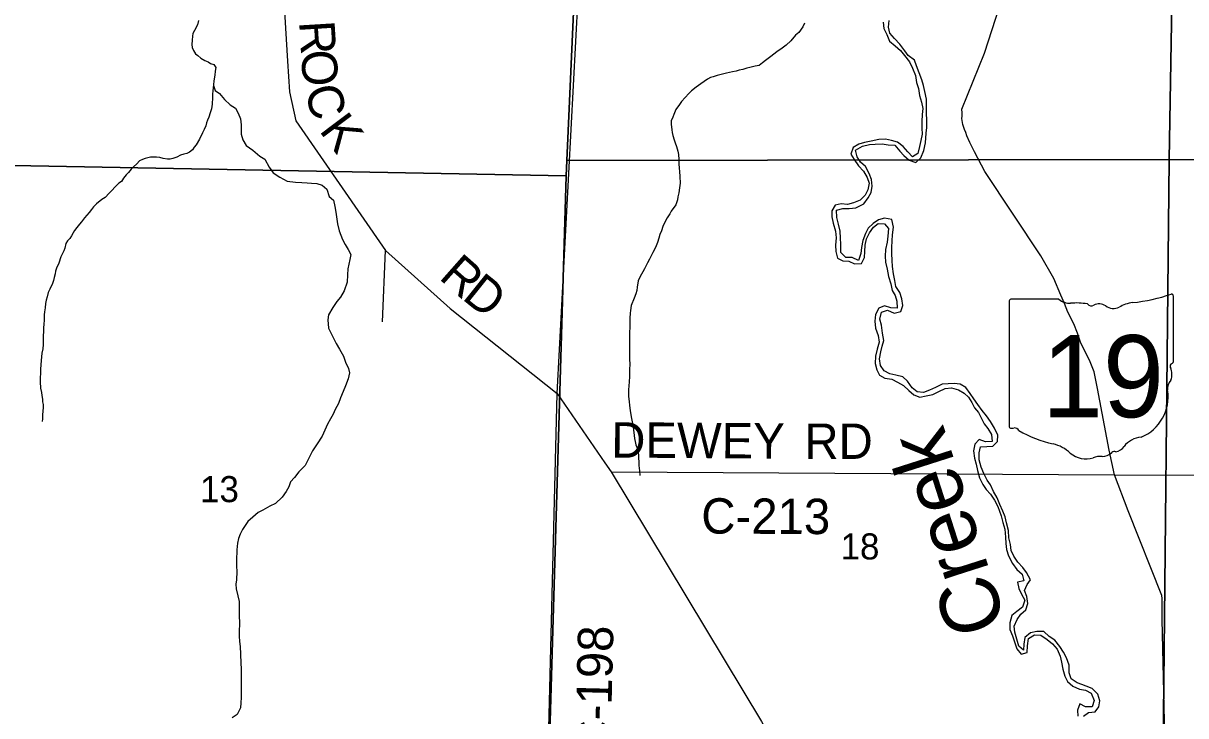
# Model space of a CAD drawing. Extents: x 0 to 34, y 0 to 22.
# Drawn here: x 25.144 to 27.011, y 17.024 to 18.136 of the extents above; entities that cross this region are included whole.
import ezdxf

# ---------------------------------------------------------------- set-up
doc = ezdxf.new("R2010")
doc.units = 0
for name, color, linetype in [('GM_X_County_Road', 7, 'Continuous'), ('GM_X_County_Road_Text', 7, 'Continuous'), ('GM_X_Minor_River', 7, 'Continuous'), ('GM_X_Minor_River_Text', 7, 'Continuous'), ('GM_X_Section', 7, 'Continuous'), ('GM_X_Section_Text', 7, 'Continuous'), ('GM_X_State_Location', 7, 'Continuous'), ('GM_X_State_Route', 7, 'Continuous'), ('GM_X_State_Shield', 7, 'Continuous'), ('GM_X_Township_Road', 7, 'Continuous')]:
    doc.layers.add(name, color=color, linetype=linetype)

msp = doc.modelspace()

# ---------------------------------------------------------------- linework, layer by layer
at = {"layer": 'GM_X_County_Road'}
for p, q in [((26.0016, 17.5418), (26.0471, 18.3979)), ((25.9854, 16.8861), (26.0016, 17.5418)), ((26.0883, 17.4156), (26.8961, 17.4108))]:
    msp.add_line(p, q, dxfattribs=at)
for points in [[(25.567, 18.4152), (25.5646, 18.2951), (25.5618, 18.1907), (25.5686, 18.0751), (25.5717, 18.0261), (25.5819, 17.9792), (25.7259, 17.7714), (25.8295, 17.6782), (26.0016, 17.5418)], [(26.0016, 17.5418), (26.078, 17.4304), (26.0883, 17.4156)], [(26.0883, 17.4156), (26.3294, 17.015), (26.4602, 16.7846), (26.4794, 16.7319), (26.4973, 16.6609), (26.566, 16.4258)], [(26.8961, 17.4108), (27.2508, 17.4104), (27.9854, 17.4096)]]:
    msp.add_lwpolyline(points, dxfattribs=at)
at = {"layer": 'GM_X_Minor_River'}
for points in [[(25.4255, 18.1407), (25.4239, 18.1335), (25.4192, 18.1248), (25.4165, 18.1199), (25.4161, 18.1157), (25.4152, 18.1089), (25.4148, 18.1021), (25.4155, 18.0975), (25.4177, 18.0922), (25.4207, 18.0872), (25.4248, 18.0842), (25.4293, 18.0799), (25.4357, 18.0764), (25.441, 18.0741), (25.4451, 18.0714), (25.4504, 18.0698), (25.4534, 18.0652), (25.4526, 18.0592), (25.4521, 18.0527), (25.4501, 18.0436), (25.4497, 18.0372), (25.4484, 18.0277), (25.448, 18.0224), (25.4479, 18.0167)], [(26.3984, 18.1363), (26.3957, 18.1303), (26.3895, 18.1216), (26.3841, 18.1168), (26.3764, 18.1081), (26.3692, 18.101), (26.3626, 18.0961), (26.3542, 18.0901), (26.3443, 18.083), (26.3359, 18.0763), (26.3309, 18.0725), (26.3259, 18.0684), (26.3195, 18.067), (26.3107, 18.0652), (26.3058, 18.0641), (26.2993, 18.0619), (26.2936, 18.0608), (26.289, 18.0593), (26.2829, 18.0579), (26.2734, 18.0561), (26.267, 18.0543), (26.2582, 18.0521), (26.2521, 18.0502), (26.2475, 18.0488), (26.2426, 18.0465), (26.2372, 18.0428), (26.2323, 18.0391), (26.2246, 18.0338), (26.2173, 18.0278), (26.2127, 18.0233), (26.2012, 18.0105), (26.1977, 18.0056), (26.192, 17.9977), (26.1885, 17.9898), (26.1869, 17.9853), (26.1845, 17.9796), (26.1845, 17.9743), (26.1855, 17.9652), (26.1862, 17.9606), (26.1873, 17.956), (26.1891, 17.9488), (26.191, 17.9439), (26.1928, 17.9385), (26.1954, 17.9305), (26.1964, 17.9252), (26.1967, 17.9172), (26.1967, 17.9104), (26.1973, 17.9036), (26.1976, 17.8979), (26.1983, 17.8903), (26.199, 17.8792), (26.1977, 17.872), (26.1969, 17.8637), (26.1949, 17.8573), (26.1945, 17.8527), (26.1921, 17.8448), (26.1844, 17.8346), (26.1825, 17.8301), (26.1778, 17.8237), (26.1736, 17.8154), (26.1712, 17.8097), (26.1689, 17.8029), (26.1665, 17.7968), (26.1649, 17.7908), (26.1626, 17.784), (26.1591, 17.7761)], [(26.5236, 17.6382), (26.522, 17.6515), (26.5196, 17.6611), (26.5222, 17.6724), (26.5318, 17.6756), (26.5423, 17.6703), (26.5534, 17.6735), (26.5563, 17.6829), (26.555, 17.6935), (26.5515, 17.7035), (26.5453, 17.7132), (26.5433, 17.7231), (26.5413, 17.7338), (26.5398, 17.7456), (26.5393, 17.7551), (26.5388, 17.7665), (26.5387, 17.776), (26.5394, 17.7866), (26.54, 17.7965), (26.5415, 17.8086), (26.5388, 17.8212), (26.5271, 17.8234), (26.5171, 17.8206), (26.509, 17.8144), (26.5009, 17.807), (26.4964, 17.7984), (26.4924, 17.7875), (26.4898, 17.7762), (26.4887, 17.7663), (26.4854, 17.7554), (26.4749, 17.7599), (26.4651, 17.7598), (26.4569, 17.768), (26.4569, 17.7816), (26.4561, 17.7912), (26.4556, 17.8022), (26.4529, 17.8133), (26.4505, 17.8243), (26.4501, 17.8361), (26.46, 17.8385), (26.4702, 17.8386), (26.4809, 17.8398), (26.4939, 17.8459), (26.5006, 17.8556), (26.5058, 17.8646), (26.5072, 17.8748), (26.506, 17.8851), (26.5025, 17.8951), (26.4963, 17.9062), (26.4886, 17.9129), (26.4831, 17.9218), (26.4804, 17.9325), (26.4915, 17.9386), (26.5026, 17.9414), (26.5121, 17.9422), (26.5231, 17.9427), (26.5329, 17.9409), (26.5435, 17.9406), (26.5516, 17.9309), (26.5582, 17.9239), (26.5668, 17.9164), (26.5773, 17.9127), (26.5851, 17.9201), (26.5899, 17.9318), (26.5925, 17.9442), (26.5941, 17.9594), (26.5951, 17.9688), (26.5947, 17.9806), (26.5946, 17.9916), (26.5945, 18.0022), (26.5944, 18.0144), (26.5917, 18.0266), (26.5893, 18.0362), (26.5869, 18.0454), (26.5827, 18.0565), (26.5784, 18.0676), (26.5749, 18.0768), (26.5652, 18.0843), (26.5594, 18.0921), (26.5513, 18.1025), (26.5432, 18.1119), (26.5355, 18.1204), (26.5335, 18.13), (26.5342, 18.1406)], [(26.525, 18.1382), (26.5259, 18.1279), (26.5309, 18.1179), (26.5348, 18.1075), (26.544, 18.0997), (26.5526, 18.0922), (26.5592, 18.0845), (26.5669, 18.0744), (26.5719, 18.064), (26.5765, 18.0521), (26.5785, 18.041), (26.5813, 18.0315), (26.5832, 18.02), (26.5864, 18.0097), (26.5884, 17.9994), (26.5873, 17.9895), (26.587, 17.9782), (26.5867, 17.9679), (26.5872, 17.958), (26.5851, 17.9478), (26.5829, 17.9384), (26.5807, 17.9271), (26.5718, 17.9216), (26.5645, 17.9298), (26.5567, 17.9384), (26.5478, 17.9451), (26.5384, 17.948), (26.5286, 17.9498), (26.5176, 17.9497), (26.5058, 17.947), (26.4951, 17.9446), (26.4859, 17.9418)], [(25.4496, 18.0362), (25.4522, 18.0284), (25.4594, 18.0234), (25.4672, 18.0135), (25.4766, 18.0054), (25.4849, 18), (25.4894, 17.992), (25.4931, 17.9828), (25.4941, 17.9733), (25.4939, 17.9578), (25.4969, 17.949), (25.5021, 17.9399), (25.513, 17.9321), (25.5239, 17.9229), (25.5322, 17.9179), (25.5392, 17.9049), (25.5456, 17.8961), (25.5561, 17.8892), (25.5682, 17.8826), (25.5814, 17.8809), (25.5917, 17.8804), (25.6, 17.88), (25.6072, 17.8795), (25.6155, 17.879), (25.6242, 17.8763), (25.6314, 17.8698), (25.6354, 17.858), (25.6425, 17.8522), (25.6447, 17.8419), (25.6461, 17.8328), (25.6486, 17.8142), (25.6515, 17.8028), (25.6566, 17.789), (25.6611, 17.781), (25.6659, 17.7726), (25.67, 17.765), (25.6688, 17.7566), (25.6652, 17.7415), (25.6647, 17.732), (25.6642, 17.7206), (25.6595, 17.7066), (25.6537, 17.6965), (25.6475, 17.6893), (25.6413, 17.6799), (25.6344, 17.6678), (25.6331, 17.6599), (25.6345, 17.6462), (25.639, 17.637), (25.6467, 17.6221), (25.652, 17.613), (25.6583, 17.6015), (25.6616, 17.592), (25.6664, 17.5817), (25.6678, 17.5745), (25.6658, 17.565), (25.6615, 17.554), (25.658, 17.5446), (25.6537, 17.5344), (25.6506, 17.5257), (25.6448, 17.5159), (25.6417, 17.5083), (25.6374, 17.5008), (25.6327, 17.4925), (25.6242, 17.4732), (25.6161, 17.4608), (25.6084, 17.4495), (25.601, 17.4347), (25.5967, 17.4261), (25.5867, 17.4155), (25.5798, 17.4065), (25.5733, 17.3994), (25.5705, 17.3918), (25.5666, 17.3839), (25.5601, 17.3748), (25.5494, 17.3651), (25.5402, 17.3606), (25.5287, 17.3539), (25.5215, 17.3506), (25.5131, 17.3431), (25.505, 17.336), (25.4962, 17.3231), (25.4927, 17.3156), (25.4899, 17.3084), (25.4883, 17.3012), (25.4871, 17.2906), (25.4865, 17.2731), (25.4868, 17.2644), (25.4874, 17.2557), (25.4865, 17.2424), (25.4853, 17.2352), (25.4863, 17.228), (25.4885, 17.2166), (25.491, 17.2074), (25.4908, 17.185), (25.4914, 17.1729), (25.4909, 17.1589), (25.4908, 17.1513), (25.4915, 17.144), (25.4925, 17.1349), (25.4931, 17.1232), (25.4937, 17.108)], [(25.4479, 18.0167), (25.4474, 18.0065), (25.4466, 17.9989), (25.4442, 17.9925), (25.4423, 17.9853), (25.4403, 17.9804), (25.4384, 17.9762), (25.4376, 17.9713), (25.4348, 17.9656), (25.4321, 17.96), (25.4271, 17.9501), (25.4217, 17.9411), (25.4186, 17.937), (25.4159, 17.9328), (25.4113, 17.9291), (25.4071, 17.9268), (25.4018, 17.9257), (25.3968, 17.9243), (25.3907, 17.9213), (25.3842, 17.9191), (25.38, 17.918), (25.3759, 17.9177), (25.3687, 17.9189), (25.3638, 17.9205), (25.3581, 17.9213), (25.3528, 17.9213), (25.3486, 17.921), (25.3444, 17.9199), (25.3398, 17.9188), (25.3357, 17.9173), (25.3311, 17.9151), (25.3265, 17.9102), (25.3211, 17.9057), (25.3173, 17.9016), (25.3134, 17.8967), (25.3096, 17.8926), (25.305, 17.8873), (25.3019, 17.882), (25.2977, 17.8794), (25.2919, 17.8734), (25.2865, 17.8674), (25.2823, 17.8633), (25.2758, 17.8565), (25.2704, 17.8531), (25.262, 17.8464), (25.257, 17.8415), (25.2539, 17.837), (25.2501, 17.8321), (25.2463, 17.828), (25.2428, 17.8238), (25.2378, 17.8174), (25.2343, 17.8133), (25.2301, 17.808), (25.2266, 17.8035), (25.2243, 17.7994), (25.2216, 17.7948), (25.2189, 17.7907), (25.2154, 17.7866), (25.2127, 17.7824), (25.2108, 17.7752), (25.2092, 17.7707), (25.2068, 17.7654), (25.2045, 17.7609), (25.2014, 17.7506), (25.1979, 17.7427), (25.1963, 17.7378), (25.1955, 17.7336), (25.1939, 17.7276), (25.1927, 17.723), (25.1911, 17.7181), (25.1872, 17.709), (25.1845, 17.7038), (25.1825, 17.697), (25.181, 17.6913), (25.1802, 17.6863), (25.1793, 17.6791), (25.1785, 17.6727), (25.178, 17.6678), (25.1776, 17.6598), (25.1771, 17.6526), (25.1767, 17.6473), (25.1764, 17.6279), (25.176, 17.6204), (25.1755, 17.6135), (25.1743, 17.6063), (25.1735, 17.6006), (25.173, 17.5946), (25.1726, 17.5878), (25.1721, 17.5805), (25.172, 17.5737), (25.1716, 17.5673), (25.1715, 17.5601), (25.1721, 17.5502), (25.1736, 17.5433), (25.1743, 17.5384), (25.175, 17.5323), (25.1753, 17.5281), (25.176, 17.5236), (25.176, 17.5186), (25.1755, 17.5137), (25.1751, 17.5065)], [(26.4859, 17.9418), (26.4767, 17.9368), (26.473, 17.9259), (26.4781, 17.9174), (26.4854, 17.9073), (26.4931, 17.8987), (26.4993, 17.8883), (26.5024, 17.8791), (26.5003, 17.8689), (26.4958, 17.8603), (26.4877, 17.8522), (26.4773, 17.8479), (26.4674, 17.8451), (26.4575, 17.8462), (26.4476, 17.8442), (26.4424, 17.8348), (26.4426, 17.8253), (26.4446, 17.815), (26.4484, 17.8024), (26.4496, 17.7913), (26.4485, 17.7796), (26.4486, 17.7697), (26.4514, 17.759), (26.46, 17.7546), (26.4698, 17.7543), (26.4788, 17.7499), (26.4898, 17.7504), (26.4946, 17.7601), (26.4953, 17.7696), (26.4959, 17.7798), (26.4981, 17.79), (26.5029, 17.7994), (26.5092, 17.8087), (26.517, 17.8145), (26.5272, 17.8143), (26.5334, 17.8065), (26.5324, 17.794), (26.5313, 17.7845), (26.5287, 17.7728), (26.5281, 17.7622), (26.5286, 17.7523), (26.5313, 17.7413), (26.5336, 17.7294), (26.5371, 17.7179), (26.5391, 17.7069), (26.5442, 17.6988), (26.547, 17.6896), (26.5474, 17.6786), (26.5372, 17.6792), (26.5267, 17.6825), (26.5178, 17.6786), (26.5123, 17.6685), (26.5116, 17.6579), (26.5124, 17.6465), (26.5167, 17.6346), (26.5183, 17.6239), (26.5153, 17.6126), (26.5123, 17.6013), (26.512, 17.5895), (26.5144, 17.5796), (26.5191, 17.5711), (26.5277, 17.566), (26.5386, 17.5645), (26.548, 17.5597), (26.5577, 17.5545), (26.5658, 17.5463), (26.574, 17.5396), (26.5837, 17.5356), (26.5937, 17.5379), (26.6043, 17.5399), (26.6143, 17.5446), (26.6243, 17.5496), (26.6346, 17.5509), (26.6455, 17.5475), (26.6548, 17.5423), (26.6619, 17.5357), (26.6673, 17.5272), (26.6716, 17.5187), (26.6779, 17.511), (26.6825, 17.5013), (26.6872, 17.4929), (26.6931, 17.4851), (26.6985, 17.4755), (26.6997, 17.4644), (26.6891, 17.4639), (26.679, 17.4676), (26.6719, 17.4599), (26.6698, 17.4497), (26.6713, 17.4375), (26.6741, 17.4283), (26.6761, 17.4176), (26.6796, 17.4061), (26.685, 17.3953), (26.6901, 17.3872), (26.6971, 17.3798), (26.7036, 17.3702), (26.7087, 17.3598), (26.714, 17.3452), (26.7171, 17.3345), (26.7202, 17.3234), (26.721, 17.3108)], [(26.1591, 17.7761), (26.1548, 17.7681), (26.1521, 17.7628), (26.1494, 17.7572), (26.1467, 17.7515), (26.1416, 17.7417), (26.1389, 17.7368), (26.1346, 17.7292), (26.1315, 17.7224), (26.1299, 17.7122), (26.1295, 17.7069), (26.1275, 17.7016), (26.1248, 17.6944), (26.1201, 17.6827), (26.1189, 17.6751), (26.1184, 17.6706), (26.118, 17.6626), (26.1182, 17.6524), (26.1182, 17.6478), (26.1177, 17.6402), (26.1173, 17.6019), (26.1176, 17.5962), (26.1179, 17.5894), (26.1178, 17.5795), (26.1173, 17.57), (26.1172, 17.5594), (26.1167, 17.5548), (26.1162, 17.5461), (26.1161, 17.537), (26.1168, 17.5283), (26.1175, 17.5226), (26.1182, 17.518), (26.1193, 17.5104), (26.1207, 17.5013), (26.1232, 17.488), (26.1239, 17.4834), (26.1249, 17.4739), (26.1256, 17.4693), (26.1267, 17.4644), (26.1278, 17.4591), (26.1304, 17.4526), (26.1318, 17.4431), (26.1321, 17.4385), (26.1328, 17.4306), (26.1327, 17.426), (26.1334, 17.4173), (26.1344, 17.4097)], [(26.5893, 17.543), (26.5794, 17.5444), (26.5716, 17.5507), (26.5636, 17.5612), (26.5566, 17.5682), (26.5453, 17.5712), (26.5355, 17.5733), (26.5265, 17.5778), (26.5207, 17.5867), (26.5191, 17.5973), (26.5212, 17.6083), (26.523, 17.6177), (26.5259, 17.6268), (26.5236, 17.6382)], [(26.8463, 17.0234), (26.8544, 17.0292), (26.8651, 17.0305), (26.8713, 17.0383), (26.8728, 17.0481), (26.8696, 17.0588), (26.8604, 17.0678), (26.8509, 17.0714), (26.8436, 17.0742), (26.836, 17.0768), (26.8267, 17.0832), (26.8235, 17.0927), (26.8235, 17.1053), (26.8189, 17.1168), (26.8142, 17.126), (26.8084, 17.1353), (26.8003, 17.1454), (26.7914, 17.1513), (26.7829, 17.1595), (26.7715, 17.1591), (26.7612, 17.1571), (26.7523, 17.1494), (26.7508, 17.1392), (26.7502, 17.1293), (26.7428, 17.1356), (26.7393, 17.1471), (26.7362, 17.1582), (26.7353, 17.1677), (26.7398, 17.1786), (26.7457, 17.1871), (26.7538, 17.1941), (26.7568, 17.2043), (26.7556, 17.2157), (26.7517, 17.2249), (26.7561, 17.2347), (26.7616, 17.2425), (26.7551, 17.2541), (26.7492, 17.2622), (26.7411, 17.2708), (26.7346, 17.2805), (26.7303, 17.2893), (26.729, 17.2988), (26.7267, 17.3099), (26.7258, 17.3217), (26.7228, 17.3339), (26.7207, 17.3435), (26.7168, 17.3523), (26.7122, 17.3631), (26.7079, 17.3742), (26.7021, 17.3842), (26.6971, 17.3946), (26.6916, 17.4024), (26.6862, 17.4128), (26.6819, 17.4231), (26.6788, 17.435), (26.6788, 17.4464), (26.6813, 17.4558), (26.6912, 17.4563), (26.7007, 17.4568), (26.7081, 17.4646), (26.7091, 17.4744), (26.7037, 17.4859), (26.6972, 17.4964), (26.6906, 17.5057), (26.6836, 17.5142), (26.6767, 17.5239), (26.6701, 17.5328), (26.6647, 17.5417), (26.6573, 17.551), (26.6484, 17.5566), (26.6386, 17.5576), (26.6291, 17.5571), (26.6196, 17.5566), (26.6088, 17.5512), (26.5992, 17.5469), (26.5893, 17.543)], [(25.1751, 17.5065), (25.175, 17.5008), (25.1746, 17.4963)], [(26.721, 17.3108), (26.7218, 17.3006), (26.7227, 17.291), (26.7259, 17.2807), (26.7324, 17.2687), (26.7393, 17.2591), (26.7482, 17.2512), (26.7509, 17.2409), (26.7406, 17.2385), (26.7426, 17.2286), (26.747, 17.2194), (26.752, 17.2094), (26.7483, 17.1981), (26.7394, 17.1915), (26.7316, 17.1849), (26.7279, 17.1732), (26.7283, 17.1626), (26.7322, 17.1522), (26.7358, 17.1426), (26.7393, 17.1315), (26.7466, 17.1229), (26.7558, 17.1253), (26.7565, 17.1363), (26.7579, 17.1481), (26.7679, 17.1539), (26.7781, 17.1532), (26.7882, 17.1465), (26.7964, 17.1394), (26.8041, 17.1309), (26.8091, 17.1197), (26.8111, 17.1102), (26.8135, 17.0987), (26.8166, 17.0876), (26.8209, 17.0788), (26.8294, 17.0713), (26.8399, 17.0668), (26.8497, 17.0651), (26.8587, 17.0603), (26.8633, 17.0487), (26.8603, 17.0382), (26.8497, 17.0385), (26.8404, 17.0433), (26.8367, 17.0328), (26.8372, 17.0233)], [(25.4937, 17.108), (25.494, 17.0996), (25.4942, 17.0852), (25.4941, 17.0757), (25.4943, 17.0613), (25.4942, 17.0533), (25.4937, 17.0446), (25.4933, 17.0366), (25.4875, 17.026), (25.4798, 17.0204)]]:
    msp.add_lwpolyline(points, dxfattribs=at)
at = {"layer": 'GM_X_Section'}
for points in [[(26.0607, 18.8928), (26.0171, 17.9156), (26.0158, 17.891), (24.9267, 17.9117), (24.9624, 18.9716)], [(27.0012, 18.9192), (26.984, 17.9172), (26.0171, 17.9156), (26.0607, 18.8928), (26.0616, 18.9227)], [(28.001, 18.9217), (27.9928, 17.9132), (26.984, 17.9172), (27.0012, 18.9192)], [(26.984, 17.9172), (26.974, 16.9197), (25.9875, 16.9239), (26.0158, 17.891), (26.0171, 17.9156)], [(27.9928, 17.9132), (27.9749, 16.9131), (26.974, 16.9197), (26.984, 17.9172)], [(26.0158, 17.891), (25.9875, 16.9239), (25.9861, 16.8906), (24.9171, 16.9109), (24.9267, 17.9117)]]:
    msp.add_lwpolyline(points, close=True, dxfattribs=at)
at = {"layer": 'GM_X_State_Route'}
msp.add_lwpolyline([(26.9826, 16.7575), (26.9729, 17.1786), (26.9726, 17.2124), (26.9723, 17.2169), (26.9182, 17.3533), (26.8961, 17.4108), (26.8874, 17.4506), (26.8687, 17.5496), (26.8638, 17.5766), (26.8561, 17.5953), (26.8447, 17.6168), (26.8418, 17.624), (26.837, 17.6385), (26.8308, 17.6534), (26.8212, 17.6722), (26.8157, 17.6859), (26.8099, 17.6993), (26.7989, 17.7264), (26.7778, 17.7628), (26.688, 17.8981), (26.6714, 17.9295), (26.6637, 17.9448), (26.6593, 17.9555), (26.6575, 17.9608), (26.6556, 17.9654), (26.6531, 17.9719), (26.6527, 17.9738), (26.6513, 17.9833), (26.6514, 17.9867), (26.6515, 17.9921), (26.6512, 17.9981), (26.6874, 18.0883), (26.7172, 18.1813)], dxfattribs=at)
at = {"layer": 'GM_X_State_Shield'}
for p, q in [((26.8068, 17.6928), (26.7296, 17.6928)), ((26.9907, 17.5931), (26.9907, 17.6978)), ((26.727, 17.6894), (26.727, 17.4893)), ((26.9907, 17.5931), (26.9907, 17.5931))]:
    msp.add_line(p, q, dxfattribs=at)
for centre, radius, start, end in [((26.73, 17.6898), 0.00305, 98.1301, 188.1301), ((26.8252, 17.7161), 0.0296, 231.6195, 271.1119), ((26.8968, 17.9657), 0.2796, 275.8445, 288.9065), ((26.9878, 17.6982), 0.00294, 351.8621, 97.738), ((26.835, 17.5805), 0.1064, 80.4867, 94.9883), ((26.8592, 17.6909), 0.00855, 219.7921, 297.1024), ((26.8717, 17.6677), 0.0178, 54.4667, 119.1411), ((26.8947, 17.6995), 0.0214, 233.8562, 294.8282), ((26.9324, 17.6317), 0.0563, 97.3462, 120.7689), ((26.99, 17.5854), 0.00454, 107.944, 210.337), ((26.9611, 17.5722), 0.0273, 340.033, 23.6496), ((26.9876, 17.5927), 0.00314, 289.6038, 7.7341), ((27.0012, 17.5493), 0.0198, 136.8065, 186.9296), ((26.9124, 17.536), 0.0699, 292.3089, 8.9858), ((26.7301, 17.4888), 0.00308, 171.9584, 258.3066), ((26.7305, 17.5093), 0.0235, 267.339, 280.6039), ((26.7354, 17.4777), 0.00848, 29.7484, 93.2717), ((26.8424, 17.6575), 0.2019, 240.4129, 257.1985), ((26.9419, 17.4331), 0.0383, 94.4031, 142.5768), ((26.7822, 17.3994), 0.0632, 47.1842, 75.836), ((26.8934, 17.4699), 0.0226, 282.8732, 323.2771), ((26.8505, 17.4767), 0.0401, 230.7004, 286.2918), ((26.8737, 17.4076), 0.0329, 85.6951, 111.2099), ((26.8766, 17.4618), 0.0214, 268.777, 315.5493), ((26.896, 17.4424), 0.00601, 65.7517, 132.6484)]:
    msp.add_arc(centre, radius, start, end, dxfattribs=at)
at = {"layer": 'GM_X_Township_Road'}
msp.add_line((25.721, 17.6564), (25.7259, 17.7714), dxfattribs=at)

# ---------------------------------------------------------------- texts
at = {"layer": 'GM_X_County_Road_Text'}
for s, height, rotation, p in [('R', 0.0568, 273.4766, (25.5871, 18.1389)), ('O', 0.0568, 273.9435, (25.5899, 18.0918)), ('C', 0.0568, 285.5303, (25.5955, 18.0296)), ('K', 0.0568, 306.946, (25.6182, 17.9639)), ('R', 0.0568, 318.5831, (25.81, 17.7268)), ('D', 0.0568, 321.2116, (25.8471, 17.6941)), ('DEWEY', 0.05682, 359.6191, (26.0881, 17.4387)), ('RD', 0.05682, 0, (26.3984, 17.4365)), ('C-213', 0.05682, 359.7247, (26.2327, 17.3166)), ('C-198', 0.05682, 88.6237, (26.0869, 16.9613))]:
    msp.add_text(s, height=height, rotation=rotation, dxfattribs=at).set_placement(p)
at = {"layer": 'GM_X_Minor_River_Text'}
msp.add_text('Creek', height=0.09474, rotation=107.7502, dxfattribs=at).set_placement((26.7238, 17.1704))
at = {"layer": 'GM_X_Section_Text'}
for s, p in [('13', (25.4282, 17.367)), ('18', (26.4565, 17.275))]:
    msp.add_text(s, height=0.04186, rotation=0, dxfattribs=at).set_placement(p)
at = {"layer": 'GM_X_State_Location'}
msp.add_text('19', height=0.000189, rotation=0, dxfattribs=at).set_placement((26.8082, 17.5623))
for s in ['s', 'r']:
    msp.add_text(s, height=0.000189, dxfattribs=at).set_placement((26.8559, 17.576))
at = {"layer": 'GM_X_State_Shield'}
msp.add_text('19', height=0.13184, dxfattribs=at).set_placement((26.7796, 17.5034))

doc.saveas('drawing.dxf')
